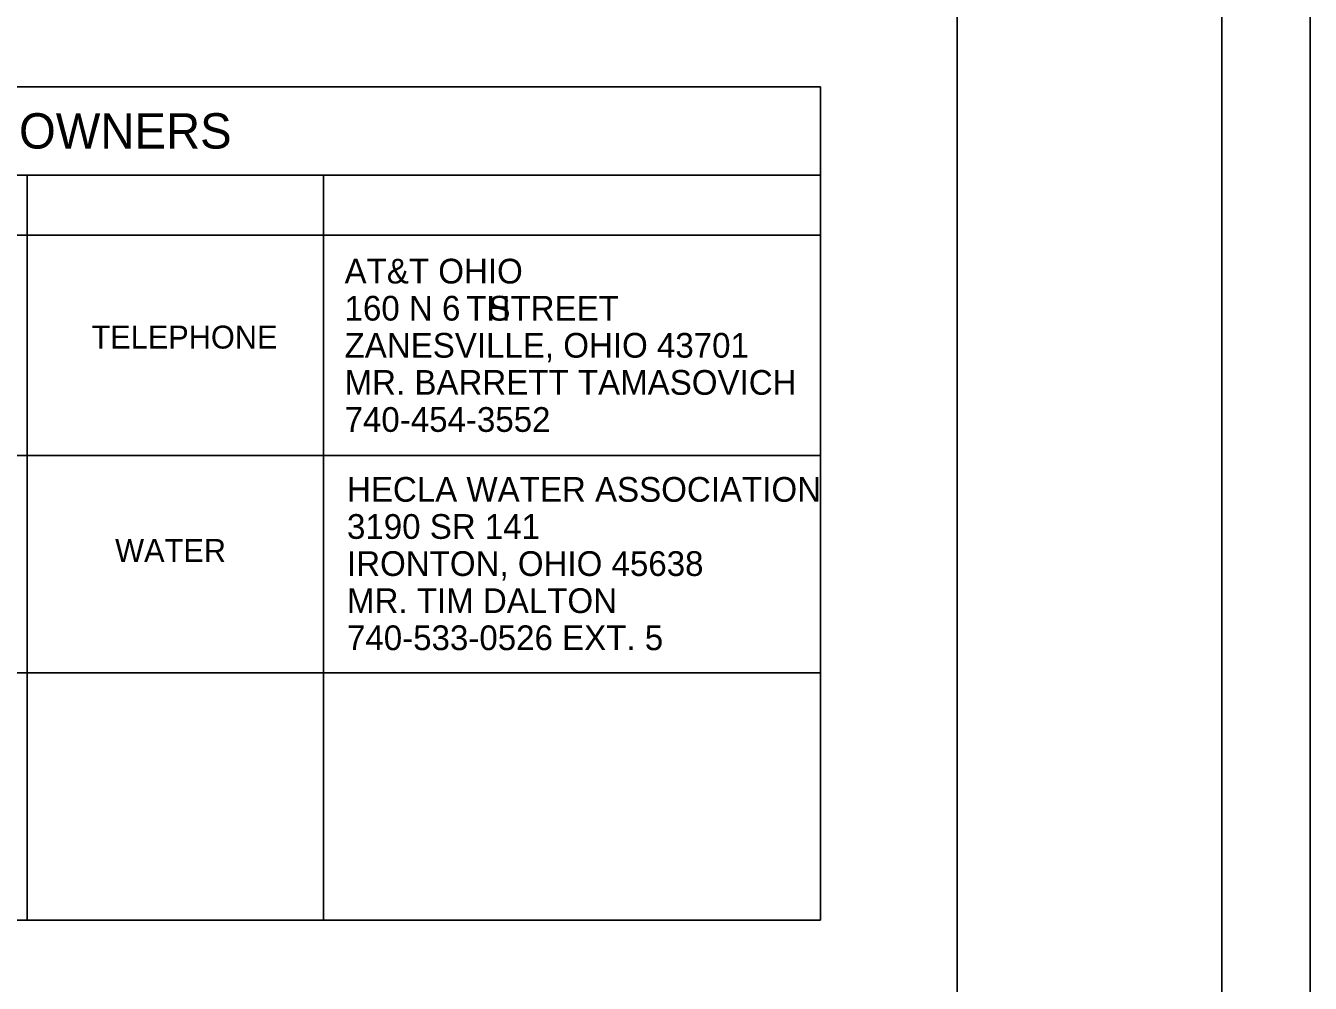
# Model space of a CAD drawing. Extents: x 0 to 34, y 0 to 22.
# Drawn here: x 26.73 to 34, y 5.54 to 10.96 of the extents above; entities that cross this region are included whole.
import ezdxf

# ---------------------------------------------------------------- set-up
doc = ezdxf.new("R2010")
doc.units = 0
for name, color, linetype in [('SH_Border', 7, 'Continuous'), ('SH_Cut_Line', 7, 'Continuous'), ('SH_Data', 7, 'Continuous'), ('SH_Text', 7, 'Continuous')]:
    doc.layers.add(name, color=color, linetype=linetype)

msp = doc.modelspace()

# ---------------------------------------------------------------- linework, layer by layer
at = {"layer": 'SH_Border'}
msp.add_line((32, 0.5), (32, 21.5), dxfattribs=at)
msp.add_lwpolyline([(1.5, 21.5), (33.5, 21.5), (33.5, 0.5), (1.5, 0.5)], close=True, dxfattribs=at)
at = {"layer": 'SH_Cut_Line'}
msp.add_lwpolyline([(0, 0), (34, 0), (34, 22), (0, 22)], close=True, dxfattribs=at)
at = {"layer": 'SH_Data'}
for p, q in [((22.2458, 10.6111), (31.2264, 10.6111)), ((31.2264, 10.6111), (31.2264, 5.8919)), ((31.2264, 10.6111), (31.2264, 5.8919)), ((22.2458, 10.1111), (31.2264, 10.1111)), ((26.7361, 10.1111), (26.7361, 5.8919)), ((28.4132, 10.1111), (28.4132, 5.8919)), ((22.2458, 9.7699), (31.2264, 9.7699)), ((22.2458, 8.5237), (31.2264, 8.5237)), ((22.2458, 7.2938), (31.2264, 7.2938)), ((22.2458, 5.8919), (31.2264, 5.8919))]:
    msp.add_line(p, q, dxfattribs=at)

# ---------------------------------------------------------------- texts
for s, p in [('TELEPHONE', (27.0994, 9.1288)), ('WATER', (27.2331, 7.9208))]:
    msp.add_text(s, height=0.13, dxfattribs=at).set_placement(p)
at = {"layer": 'SH_Text'}
for s, height, p in [('UTILITY OWNERS', 0.2, (25.6193, 10.2611)), ('AT&T OHIO', 0.14, (28.5323, 9.4972)), ('160 N 6', 0.14, (28.5323, 9.2872)), ('TH', 0.14, (29.2211, 9.2872)), (' STREET', 0.14, (29.2945, 9.2872)), ('ZANESVILLE, OHIO 43701', 0.14, (28.5323, 9.0772)), ('MR. BARRETT TAMASOVICH', 0.14, (28.5323, 8.8672)), ('740-454-3552', 0.14, (28.5323, 8.6572)), ('HECLA WATER ASSOCIATION', 0.14, (28.546, 8.2615)), ('3190 SR 141', 0.14, (28.546, 8.0515)), ('IRONTON, OHIO 45638', 0.14, (28.546, 7.8415)), ('MR. TIM DALTON', 0.14, (28.546, 7.6315)), ('740-533-0526 EXT. 5', 0.14, (28.546, 7.4215))]:
    msp.add_text(s, height=height, dxfattribs=at).set_placement(p)

doc.saveas('drawing.dxf')
